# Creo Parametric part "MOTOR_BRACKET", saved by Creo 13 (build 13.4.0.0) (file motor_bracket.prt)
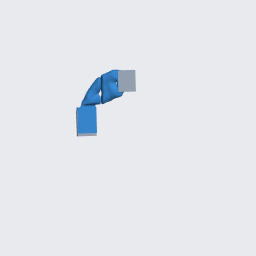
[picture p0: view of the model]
Units: millimeter Newton Second (mmNs); MM, TONNE, SECS
Materials in the file: PLA

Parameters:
  GRANTA_DATALINK_VERSION = "5"
  GRANTA_DATABASE_KEY = "Granta_Typical_Materials"
  GRANTA_IDENTITY_GUID = "b9b893b2-6906-4609-ab08-d879fcb43028"
  GRANTA_VERSION_GUID = "46d219ad-0776-45d4-90e4-94de701ee33b"
  GRANTA_MODEL_REFERENCE = "00000000-0000-0000-0000-000000000000"

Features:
  1. datum plane "RIGHT"
  2. datum plane "TOP"
  3. datum plane "FRONT"
  4. coordinate system
  5. protrusion
  6. datum plane "DEFAULT_1"
  7. protrusion
  8. protrusion
  9. datum plane "DEFAULT_2"
  10. protrusion

Other named items: PRT_CSYS_DEF_1, PRT_CSYS_DEF_2, PRT_CSYS_DEF_3, PRT_CSYS_DEF_4, PRT_CSYS_DEF_5, PRT_CSYS_DEF_6, PRT_CSYS_DEF_7, PRT_CSYS_DEF_8, PRT_CSYS_DEF_1_1, PRT_CSYS_DEF_2_1, PRT_CSYS_DEF_3_1, PRT_CSYS_DEF_4_1, GENERATIVE_HYBRID, RECONSTRUCTED_GEOMETRY

Surfaces: 45 plane, 17 cylinder, 2 torus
